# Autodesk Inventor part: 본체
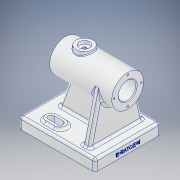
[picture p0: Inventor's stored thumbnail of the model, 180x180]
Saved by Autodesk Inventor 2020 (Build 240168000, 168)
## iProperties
Created: 2021-11
Part Number: 본체
Material: 알루미늄 6061
Document SubType Name: Modeling
Designer: user
Density: 2.7 g/cm^3
Appearance: 알루미늄 - 평지
Mass: 633.827 g
Surface Area: 513.467 cm^2
Volume: 234.751 cm^3
Author: user
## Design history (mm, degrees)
sketch "스케치1"
  geometry: L1 (0, 0)-(82, 0); L2 (0, 14.5)-(0, 21); L3 (0, 21)-(82, 21); L4 (82, 21)-(82, 11.5); L5 (82, 11.5)-(62, 11.5); L6 (62, 11.5)-(62, 14.5); L7 (62, 14.5)-(0, 14.5); 2 further points
  constraints: 14 end point, 5 perpendicular, 2 midpoint, 2 vertical alignment, 1 horizontal, 1 vertical
  dimensions: "d0" = 82 distance of L1.start L1.end; "d1" = 42 diameter of L3 L1; "d2" = 29 diameter of L7 L1; "d3" = 23 diameter of L5 L1; "d4" = 62 distance of L2.start L6.end
revolve "회전1" sketch "스케치1" stored, may be unused: angle "d5" = 90 deg
node "작업 평면1"
sketch "스케치2"
  geometry: C1 r 11 at (-25, 0); 1 further point
  constraints: 1 centre point, 1 horizontal alignment
  dimensions: "d7" = 22 diameter of C1; "d8" = 25 distance of point (0, 0) C1.centre
extrude "돌출1" join sketch "스케치2" stored distance "d9" = 10; taper "d10" = 0 deg
sketch "스케치3"
  geometry: C1 r 11 at (0, 0) reference; C2 r 7 at (0, 0); 1 further point
  constraints: 1 centre point, 1 coincident
  dimensions: "d11" = 14 diameter of C2
extrude "돌출2" cut sketch "스케치3" distance "d12" = 4; taper "d13" = 0 deg
sketch "스케치4"
  geometry: C1 r 7 at (0, 0) reference; 2 further points
  constraints: 1 coincident
hole "구멍1" sketch "스케치4" at (0, 0) diameter "d14" = 4.917; stored, may be unused: countersink angle "d18" = 90 deg, drill point angle "d20" = 0 deg; dims "d15" = 12, "d16" = 4, "d17" = 2, "d19" = 17.1
node "작업 평면2"
sketch "스케치5"
  geometry: L1 (-82, 21)-(-82, -21) reference; L2 (-82, 0)-(-82, -43); L3 (-82, -43)-(18, -43); L4 (18, -43)-(18, 43); L5 (18, 43)-(-82, 43); L6 (-82, 43)-(-82, 0); 3 further points
  constraints: 10 end point, 2 perpendicular, 1 collinear, 1 midpoint, 1 point on line
  dimensions: "d22" = 43 distance of L2.start L2.end; "d23" = 100 distance of L2.end L3.end; "d24" = 86 distance of L3.end L4.end; "d25" = 100 distance of L4.end L5.end
extrude "돌출3" join sketch "스케치5" distance "d26" = 15; taper "d27" = 0 deg
node "작업 평면3"
sketch "스케치8"
  geometry: L1 (-57, -43)-(-72, -43) reference; L2 (-72, -43)-(-72, 43) reference; L3 (-72, 43)-(-57, 43) reference; L4 (-57, 43)-(-57, -43) reference; L5 (4.814, 20.441)-(-57, 35); L6 (-57, 43)-(-57, -43) reference; L7 (-57, -35)-(4.814, -20.441); C1 r 14.5 at (0, 0) reference; C2 r 21 at (0, 0) reference; C3 r 11.5 at (0, 0) reference; A1 r 21 centre (0, 0) between (4.814, 20.441) and (4.814, -20.441) reference; 5 further points
  constraints: 4 end point, 2 point on circle, 2 point on line, 2 tangent
  dimensions: "d31" = 8 distance from line of L3 L5.end; "d32" = 8 distance from line of L1 L7.start
extrude "돌출4" join sketch "스케치8" stored distance "d33" = 10; taper "d34" = 0 deg
sketch "스케치11"
  geometry: L1 (10.103, -21)-(-3, -57); L2 (14, 21)-(14, 24) reference; L3 (14, 24)-(18, 24) reference; L4 (18, 24)-(18, 20) reference; L5 (18, 20)-(22.541, 20) reference; L6 (22.541, 20)-(22.541, 14.5) reference; L7 (22.541, 14.5)-(0, 14.5) reference; L8 (0, 14.5)-(0, 21) reference; L9 (0, 21)-(14, 21) reference; L10 (36, 24)-(36, 21) reference; L11 (36, 21)-(82, 21) reference; L12 (82, 21)-(82, 11.5) reference; L13 (82, 11.5)-(62, 11.5) reference; L14 (62, 11.5)-(62, 14.5) reference; L15 (62, 14.5)-(27.459, 14.5) reference; L16 (27.459, 14.5)-(27.459, 20) reference; L17 (27.459, 20)-(32, 20) reference; L18 (32, 20)-(32, 24) reference; L19 (32, 24)-(36, 24) reference; L20 (0, -14.5)-(62, -14.5) reference; L21 (62, -14.5)-(62, -11.5) reference; L22 (62, -11.5)-(82, -11.5) reference; L23 (82, -11.5)-(82, -21) reference; L24 (82, -21)-(67, -21) reference; L25 (67, -21)-(67, -57) reference; L26 (67, -57)-(82, -57) reference; L27 (82, -57)-(82, -72) reference; L28 (82, -72)-(-18, -72) reference; L29 (-18, -72)-(-18, -57) reference; L30 (-18, -57)-(57, -57) reference; L31 (57, -57)-(57, -21) reference; L32 (57, -21)-(0, -21) reference; L33 (0, -21)-(0, -14.5) reference; 1 further point
  constraints: 2 end point, 2 point on line
  dimensions: "d35" = 15 distance from line of L29 L1.end; "d37" = 70 deg angle of L30 L1
  node "절단 모서리 투영3"
sketch "스케치12"
  geometry: L1 (82, 43)-(-18, 43) reference; L2 (8, 27)-(20, 27); L3 (8, 20)-(20, 20); L4 (20, 34)-(8, 34); L5 (-18, 43)-(-18, -43) reference; A1 r 7 centre (8, 27) between (8, 34) and (8, 20); A2 r 7 centre (20, 27) between (20, 20) and (20, 34); 2 further points
  constraints: 8 end point, 4 point on circle, 4 tangent, 2 centre point, 1 horizontal, 1 midpoint, 1 parallel
  dimensions: "d41" = 12 distance of L2.start L2.end; "d42" = 26 distance from line of L5 L2.start; "d43" = 27 vertical distance of point (0, 0) point (14, 27); "d44" = 14 distance between parallel lines of L3 L4
extrude "돌출6" join sketch "스케치12" distance "d45" = 3; taper "d46" = 0 deg
sketch "스케치15"
  geometry: L1 (8, 27)-(20, 27); L2 (8, 23)-(20, 23); L3 (20, 31)-(8, 31); L4 (8, -27)-(20, -27); L5 (8, -31)-(20, -31); L6 (20, -23)-(8, -23); A1 r 7 centre (8, 27) between (8, 34) and (8, 20) reference; A2 r 7 centre (20, 27) between (20, 20) and (20, 34) reference; A3 r 4 centre (8, 27) between (8, 31) and (8, 23); A4 r 4 centre (20, 27) between (20, 23) and (20, 31); A5 r 7 centre (8, -27) between (8, -20) and (8, -34) reference; A6 r 7 centre (20, -27) between (20, -34) and (20, -20) reference; A7 r 4 centre (8, -27) between (8, -23) and (8, -31); A8 r 4 centre (20, -27) between (20, -31) and (20, -23); 3 further points
  constraints: 16 end point, 8 point on circle, 8 tangent, 4 centre point, 2 horizontal, 2 midpoint, 2 parallel
  dimensions: "d50" = 8 diameter of A4; "d51" = 8 diameter of A8
extrude "돌출7" cut sketch "스케치15" distance "d52" = 33.75; taper "d53" = 0 deg
sketch "스케치16"
  geometry: 2 further points
  constraints: 1 vertical alignment
  dimensions: "d54" = 18 distance of point (0, 0) point (0, 18)
hole "구멍2" sketch "스케치16" at (0, 18) diameter "d55" = 2.459; stored, may be unused: countersink angle "d59" = 90 deg, drill point angle "d61" = 0 deg; dims "d56" = 8, "d57" = 4, "d58" = 2, "d60" = 10
sketch "스케치18"
  geometry: 2 further points
  constraints: 1 vertical alignment
  dimensions: "d65" = 18 distance of point (0, 0) point (0, 18)
feature "리브1" dims "d66" = 1, "d67" = 10, "d68" = 0, "d69" = 0, "d70" = 1, "d71" = 1
hole "구멍3" sketch "스케치18" diameter "d72" = 2.459; stored, may be unused: countersink angle "d76" = 90 deg, drill point angle "d78" = 0 deg; dims "d73" = 8, "d74" = 4, "d75" = 2, "d77" = 10
fillet "모깎기1" dims "d82" = 3
fillet "모깎기2" dims "d83" = 3
fillet "모깎기3" dims "d84" = 3
chamfer "모따기1" distance "d85" = 1; stored, may be unused: second distance "d86" = 2, angle "d87" = 45 deg
fillet "모깎기4" dims "d88" = 3
fillet "모깎기5" dims "d89" = 3
fillet "모깎기6" dims "d90" = 1
sketch "스케치19"
  geometry: L1 (0, 0)-(80, 0) reference; 2 further points
  constraints: 1 vertical alignment, 1 other
  dimensions: "d91" = 6 distance from line of L1 point (40, 6)
feature "엠보싱1" sketch "스케치19" dims "d92" = 0.5, "d93" = 0
node "솔리드1"
pattern_linear "직사각형 패턴1" dims "d49" = 54
pattern_circular "원형 패턴1" dims angle "d63" = 360 deg
pattern_circular "원형 패턴2" dims angle "d80" = 360 deg
node "절단 모서리 투영2"
feature "A9D066F2-1C7D-4E18-AEED-F7BC21143FA4" dims "d14" = 4.917, "d15" = 12, "d16" = 4, "d17" = 2, "d18" = 90 deg, "d19" = 17.1, "d20" = 0
other parameters: "d6" = 24, "d21" = -72, "d28" = 62
